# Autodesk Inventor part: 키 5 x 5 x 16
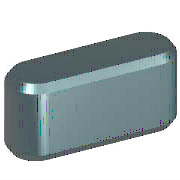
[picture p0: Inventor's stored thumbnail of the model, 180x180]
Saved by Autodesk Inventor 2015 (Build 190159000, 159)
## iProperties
IsCustomPart: 1
Created: 2012-02
Part Number: 키 5 x 5 x 16
Material: 강철, 연강
Description: 키 및 해당 키홈
Document SubType Name: Modeling
Standard: KS B 1311
Designer: mduedu
Standards Organization: KS
Language: ko-KR
Size Designation: 5 x 5 x 16
Categories: <MemberInstance><Categories><Category DisplayName="샤프트 부품" InternalName="7f7aeb1f-a693-4053-b835-cee3144e0d98" Mnemonic="SHFT"><Category DisplayName="키" Interna
Density: 1 g/cm^3
Appearance: 강철
Author: mduedu
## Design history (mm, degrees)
workplane "Work Plane1"
workplane "Work Plane2"
sketch "스케치1"
  geometry: L1 (2.5, 2.5)-(13.5, 2.5); L2 (13.5, -2.5)-(2.5, -2.5); L3 (0, 9.4)-(0, -7.4) reference; L4 (-5, 0)-(30, 0) reference; L5 (16, 0)-(16, 7); A1 r 2.5 centre (2.5, 0) between (2.5, 2.5) and (2.5, -2.5); A2 r 2.5 centre (13.5, 0) between (13.5, -2.5) and (13.5, 2.5)
  constraints: 6 end point, 5 point on circle, 4 tangent, 3 point on line, 2 centre point, 1 horizontal, 1 parallel, 1 perpendicular
  dimensions: "d0" = 2.5 radius of A1 (= 0.5 x PB); "d13" = 2.5 radius of A2 (= 0.5 x PB); "d14" = 16 distance between parallel lines of L5 L3 (= NLG)
extrude "본체1" new body sketch "스케치1" taper "d3" = 0 deg; stored distance "d4" = 10
workplane "Work Plane3"
body "Solid1"
chamfer "모따기1" distance "d8" = 0.4 (= PHH); stored, may be unused: second distance "d9" = 0.4 (= PHH), angle "d15" = 45 deg
other parameters: "d1" = -3 (= -PNT), "d2" = 2 (= PH - PNT), "NLG" = 16 [user parameter; used in 3 equation terms], "PB" = 5 [user parameter; used in 2 equation terms], "PNT" = 3 [user parameter; used in 2 equation terms], "PH" = 5 [user parameter; used in 1 equation term], "PHH" = 0.4 [user parameter; used in 2 equation terms], "d10" = 0, "d16" = 0, "d17" = 0, "d18" = 0, "WDMIN" = 12 [user parameter], "PLB2" = 16 (= NLG) [user parameter], "WDMAX" = 17 [user parameter], "PLB1" = 16 (= NLG) [user parameter], "RR" = 0.16 [user parameter], "PUEB" = 2.3 [user parameter]
